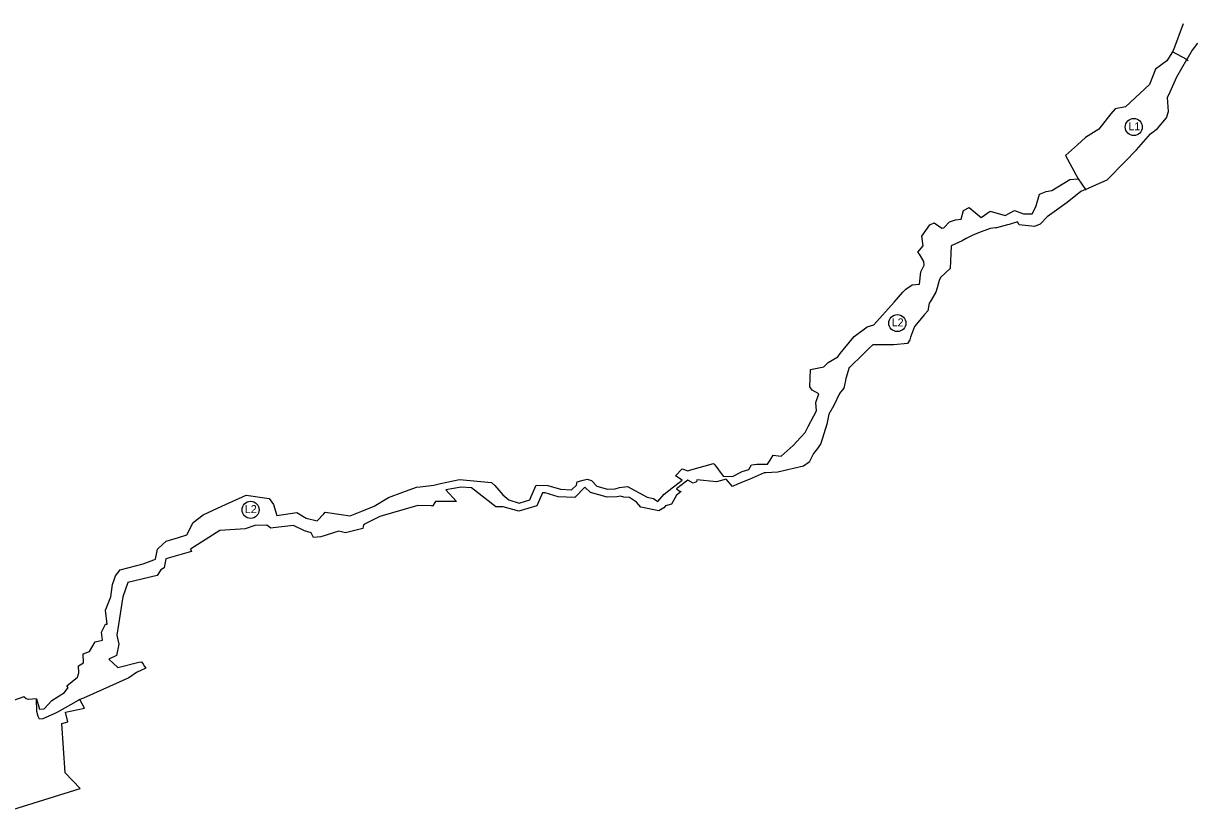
# Model space of a CAD drawing. Extents: x -445081 to -434932, y -1146827 to -1130103.
# Drawn here: x -442214 to -440454, y -1132548 to -1131370 of the extents above; entities that cross this region are included whole.
import ezdxf

# ---------------------------------------------------------------- set-up
doc = ezdxf.new("R2010")
doc.units = 0
for name, color, linetype in [('Vrstva 32', 7, 'Continuous'), ('Vrstva 33', 7, 'Continuous'), ('Vrstva 36', 7, 'Continuous')]:
    doc.layers.add(name, color=color, linetype=linetype)

msp = doc.modelspace()

# ---------------------------------------------------------------- linework, layer by layer
at = {"layer": 'Vrstva 32'}
for points in [[(-440621.7, -1131619.1), (-440605.4, -1131611.9), (-440589, -1131604.6), (-440562.6, -1131577.8), (-440545.4, -1131559.7), (-440524.2, -1131535.8), (-440513.9, -1131527.8), (-440500.5, -1131511.6), (-440497.2, -1131502.5), (-440498.7, -1131481.2), (-440494.9, -1131472.7), (-440485, -1131450.2), (-440469.9, -1131424.5), (-440491.3, -1131412.9), (-440500, -1131426.5), (-440516.8, -1131438.7), (-440525.6, -1131461.9), (-440561.9, -1131495.4), (-440577.2, -1131498.3), (-440583.6, -1131505.7), (-440601.8, -1131528.9), (-440621.5, -1131541.1), (-440633.6, -1131552.1), (-440651.5, -1131568.4), (-440632.8, -1131603.4), (-440621.7, -1131619.1)], [(-440468, -1131426.4), (-440469.9, -1131424.5), (-440491.3, -1131412.9), (-440500, -1131426.5), (-440516.8, -1131438.7), (-440525.6, -1131461.9), (-440561.9, -1131495.4), (-440577.2, -1131498.3), (-440583.6, -1131505.7), (-440601.8, -1131528.9), (-440601.8, -1131528.9), (-440621.5, -1131541.1), (-440633.6, -1131552.1), (-440651.5, -1131568.4), (-440632.8, -1131603.4), (-440621.7, -1131619.1), (-440621.9, -1131620.3)], [(-442230.4, -1132548.5), (-442129.2, -1132516.8), (-442151.6, -1132493.3), (-442156.8, -1132419.4), (-442147.8, -1132417.1), (-442151.1, -1132402.4), (-442122.6, -1132396.7), (-442129.7, -1132383.8), (-442132.1, -1132384.9), (-442163.5, -1132402.4), (-442166.4, -1132404.1), (-442185.4, -1132412.8), (-442190.5, -1132413.2), (-442190.5, -1132413.2), (-442192.4, -1132409.2), (-442194.2, -1132401.6), (-442194.6, -1132382.5), (-442206.7, -1132383.5), (-442210.1, -1132382.7), (-442213.7, -1132379.6), (-442303.1, -1132411)], [(-442230.4, -1132548.5), (-442129.2, -1132516.8), (-442151.6, -1132493.3), (-442156.8, -1132419.4), (-442147.8, -1132417.1), (-442151.1, -1132402.4), (-442122.6, -1132396.7), (-442129.7, -1132383.8), (-442132.1, -1132384.9), (-442163.5, -1132402.4), (-442166.4, -1132404.1), (-442185.4, -1132412.8), (-442190.5, -1132413.2), (-442192.4, -1132409.2), (-442194.2, -1132401.6), (-442194.6, -1132382.5), (-442206.7, -1132383.5), (-442210.1, -1132382.7), (-442213.7, -1132379.6), (-442303.1, -1132411)]]:
    msp.add_lwpolyline(points, dxfattribs=at)
at = {"layer": 'Vrstva 33'}
for points in [[(-440491.3, -1131412.9), (-440489.2, -1131409.3), (-440475, -1131370.4)], [(-440453.7, -1131400.1), (-440461.6, -1131410.5), (-440469.9, -1131424.5)], [(-442194.6, -1132382.5), (-442190.4, -1132398.3), (-442183.1, -1132397.7), (-442172, -1132385.1), (-442152.9, -1132373.3), (-442147.1, -1132365.7), (-442149.2, -1132363), (-442133.5, -1132350.3), (-442131.5, -1132343.5), (-442131.9, -1132333.2), (-442124.4, -1132328.7), (-442124.8, -1132315.1), (-442115.4, -1132311.6), (-442106.8, -1132297.2), (-442095.8, -1132294.5), (-442097.1, -1132282.6), (-442091.2, -1132270.8), (-442088.8, -1132270.5), (-442091.5, -1132249.7), (-442083.1, -1132229.6), (-442080.6, -1132211.1), (-442077.8, -1132202.9), (-442076.1, -1132198.1), (-442069.2, -1132189.5), (-442035, -1132180.3), (-442018.8, -1132174.2), (-442016.2, -1132173.2), (-442013.2, -1132158.4), (-442005.7, -1132151.3), (-442000.4, -1132146.2), (-441982, -1132140.6), (-441969.2, -1132136.8), (-441960.1, -1132118.1), (-441944.8, -1132106.9), (-441916.7, -1132094), (-441880.5, -1132077.3), (-441846.1, -1132082.3), (-441839.3, -1132091.3), (-441834.4, -1132107.8), (-441804.5, -1132103.5), (-441790.2, -1132111.6), (-441774.1, -1132116), (-441764, -1132105.2), (-441761.9, -1132102.9), (-441737.8, -1132106.4), (-441724.3, -1132108.4), (-441707.1, -1132101.5), (-441688.2, -1132093.9), (-441666.7, -1132080.9), (-441666.7, -1132080.9), (-441645.6, -1132073.1), (-441624.9, -1132065.5), (-441619.7, -1132064.9), (-441598.9, -1132062.3), (-441588.8, -1132060.1), (-441560.3, -1132053.8), (-441560.3, -1132053.8), (-441512.7, -1132058.4), (-441507.3, -1132062.7), (-441495.4, -1132076.7), (-441486.6, -1132084.3), (-441471.1, -1132089.4), (-441461.3, -1132086.4), (-441455.2, -1132084.4), (-441452.8, -1132079.2), (-441445.3, -1132062.4), (-441428, -1132062.8), (-441409.1, -1132068.6), (-441392.3, -1132069.2), (-441385.1, -1132062.4), (-441384.1, -1132057.4), (-441374.9, -1132054.9), (-441369, -1132053.3), (-441362.3, -1132055.5), (-441354.7, -1132063.7), (-441338.6, -1132068.6), (-441326.8, -1132067.9), (-441320.6, -1132065.8), (-441308.5, -1132064.4), (-441278.9, -1132080.2), (-441269.4, -1132082.5), (-441262.8, -1132086.8), (-441253.7, -1132075.8), (-441239.5, -1132065), (-441226.4, -1132055.1), (-441236.6, -1132048.6), (-441226.5, -1132037.9), (-441217.9, -1132040.7), (-441213.5, -1132039.4), (-441179.8, -1132029.7), (-441177.8, -1132031.7), (-441165.2, -1132048.9), (-441150.9, -1132049.3), (-441136.7, -1132041.7), (-441126.6, -1132038.8), (-441122.7, -1132032.1), (-441114.6, -1132030.8), (-441098.6, -1132031.1), (-441094.8, -1132025), (-441089.9, -1132017.2), (-441078.3, -1132019), (-441060.2, -1132002.9), (-441048.4, -1131990.2), (-441042.2, -1131983.6), (-441037.4, -1131974.5), (-441028.9, -1131958.4), (-441025, -1131951.1), (-441025.9, -1131938.6), (-441021.4, -1131925.4), (-441031.5, -1131920.1), (-441034.9, -1131915.1), (-441034, -1131888.8), (-441014.3, -1131885), (-441007.7, -1131878.7), (-440993.3, -1131869.9), (-440989.8, -1131864.8), (-440968.7, -1131839.4), (-440949.2, -1131825), (-440938.9, -1131821.9), (-440908.7, -1131788.1), (-440895.4, -1131773.2), (-440891.4, -1131768.6), (-440881.6, -1131762.1), (-440870.8, -1131761.1), (-440868.7, -1131742.5), (-440863.7, -1131732.5), (-440864.1, -1131727.1), (-440870.6, -1131716.2), (-440873.4, -1131713), (-440865.1, -1131703.6), (-440867.4, -1131689.1), (-440855.4, -1131672.4), (-440848.8, -1131669.1), (-440837.4, -1131677.1), (-440834.2, -1131676.6), (-440825.8, -1131667.6), (-440816.9, -1131664.7), (-440808.4, -1131663.5), (-440804.9, -1131650.9), (-440796, -1131646.4), (-440778.3, -1131661.4), (-440764.6, -1131651.8), (-440742.4, -1131658.1), (-440728.1, -1131650.9), (-440714.9, -1131655.9), (-440701.7, -1131655.9), (-440696.3, -1131645.4), (-440690.6, -1131626.1), (-440680.6, -1131622.2), (-440672, -1131620.7), (-440645, -1131604.4), (-440632.8, -1131603.4)], [(-440621.7, -1131619.1), (-440628.8, -1131622.3), (-440649, -1131638.6), (-440679.3, -1131660.1), (-440689.7, -1131671.4), (-440698, -1131674.9), (-440721.1, -1131672.4), (-440723.8, -1131667.7), (-440736.4, -1131671.8), (-440738.9, -1131672.4), (-440755.4, -1131676.6), (-440756.6, -1131676.9), (-440764.7, -1131677.9), (-440782, -1131684.4), (-440788.3, -1131686.7), (-440791.8, -1131688), (-440800.5, -1131692.6), (-440806.8, -1131696), (-440823.2, -1131703.7), (-440824.8, -1131737.5), (-440839.3, -1131751), (-440841.2, -1131755.6), (-440844.3, -1131766.8), (-440846, -1131773.1), (-440854.8, -1131787.8), (-440856, -1131789.8), (-440858.1, -1131801), (-440863.5, -1131807.3), (-440872.7, -1131818), (-440878.2, -1131824.4), (-440884, -1131840.7), (-440885.4, -1131844.5), (-440888.9, -1131850.3), (-440908.9, -1131852.2), (-440920.2, -1131852.2), (-440930.5, -1131851.9), (-440940.4, -1131852), (-440946.3, -1131857.1), (-440948, -1131858.8), (-440952.1, -1131863), (-440959.6, -1131870.7), (-440971, -1131881.6), (-440975.7, -1131886), (-440975.9, -1131886.1), (-440980.9, -1131902.3), (-440982.2, -1131907.9), (-440982.7, -1131910.1), (-440984.3, -1131917.1), (-440990.5, -1131925.2), (-440999.2, -1131943.1), (-441006.5, -1131955.8), (-441009.7, -1131971), (-441018.5, -1132000.1), (-441023.7, -1132007.3), (-441029.6, -1132014.7), (-441033.8, -1132022.8), (-441036.3, -1132027.7), (-441044.8, -1132033.9), (-441083.1, -1132042.9), (-441101.3, -1132043.8), (-441103.5, -1132043.9), (-441126.3, -1132054), (-441142.4, -1132060.6), (-441151, -1132064.2), (-441160.5, -1132053.4), (-441174.9, -1132057.4), (-441204.5, -1132054.6), (-441205.1, -1132057.6), (-441210, -1132059.4), (-441218.3, -1132055.1), (-441222, -1132057.9), (-441235.2, -1132067.9), (-441235.2, -1132067.9), (-441229.8, -1132071.7), (-441228, -1132072.1), (-441235.2, -1132077.6), (-441242.5, -1132091.1), (-441251.6, -1132093.5), (-441254.3, -1132096.3), (-441261.4, -1132100.6), (-441288.3, -1132095.2), (-441294.8, -1132087.9), (-441296.5, -1132086.8), (-441305.4, -1132081), (-441314, -1132080.3), (-441314, -1132080.3), (-441314, -1132080.3), (-441319.2, -1132078.8), (-441319.2, -1132078.8), (-441324.3, -1132079.7), (-441338.8, -1132080.6), (-441363.8, -1132073.4), (-441372.5, -1132065.4), (-441387.6, -1132080.9), (-441412.7, -1132079.8), (-441431.9, -1132073.7), (-441436.2, -1132073.7), (-441444.7, -1132093.2), (-441471.3, -1132101.5), (-441495.2, -1132094.8), (-441506.2, -1132094.7), (-441542.7, -1132066.2), (-441557.9, -1132065.2), (-441580.8, -1132069.2), (-441565.2, -1132086.9), (-441596.6, -1132087.1), (-441596.6, -1132087.1), (-441601, -1132094.1), (-441601, -1132094.1), (-441602.3, -1132093.3), (-441623, -1132093), (-441679.7, -1132109.1), (-441679.7, -1132109.1), (-441703.9, -1132121.1), (-441704.7, -1132124.2), (-441705.4, -1132127.2), (-441731.3, -1132133.9), (-441741.6, -1132131.3), (-441768.2, -1132139.7), (-441779.6, -1132140.8), (-441782.8, -1132133.6), (-441792.7, -1132130.8), (-441809.2, -1132122.8), (-441839.7, -1132126.2), (-441843.4, -1132126.6), (-441849.5, -1132122.5), (-441867.2, -1132122.8), (-441881.8, -1132128), (-441919.7, -1132130.2), (-441925.5, -1132133.9), (-441963.7, -1132158.2), (-441962.5, -1132161.6), (-442000.9, -1132172.9), (-442003.5, -1132186.2), (-442008.5, -1132189.4), (-442013.7, -1132197.7), (-442057.7, -1132208.4), (-442065.5, -1132229.9), (-442071.7, -1132271.2), (-442074.1, -1132287), (-442071.5, -1132300.9), (-442074.6, -1132317.9), (-442086.4, -1132323), (-442072.7, -1132335.8), (-442041.1, -1132327.7), (-442037.4, -1132327.3), (-442034.9, -1132330.7), (-442032.7, -1132334), (-442030.8, -1132336.4), (-442045, -1132342.9), (-442056.5, -1132350.9), (-442124.4, -1132381.4), (-442129.7, -1132383.8)]]:
    msp.add_lwpolyline(points, dxfattribs=at)
at = {"layer": 'Vrstva 36'}
for centre in [(-440549.3, -1131525.6), (-440903.9, -1131819.5), (-441873.7, -1132099.3)]:
    msp.add_circle(centre, 12.8, dxfattribs=at)

# ---------------------------------------------------------------- texts
for s, p in [('L1', (-440557.4, -1131530.6)), ('L2', (-440912.4, -1131824.4)), ('L2', (-441882.3, -1132104.2))]:
    msp.add_text(s, height=12, dxfattribs=at).set_placement(p)

doc.saveas('drawing.dxf')
